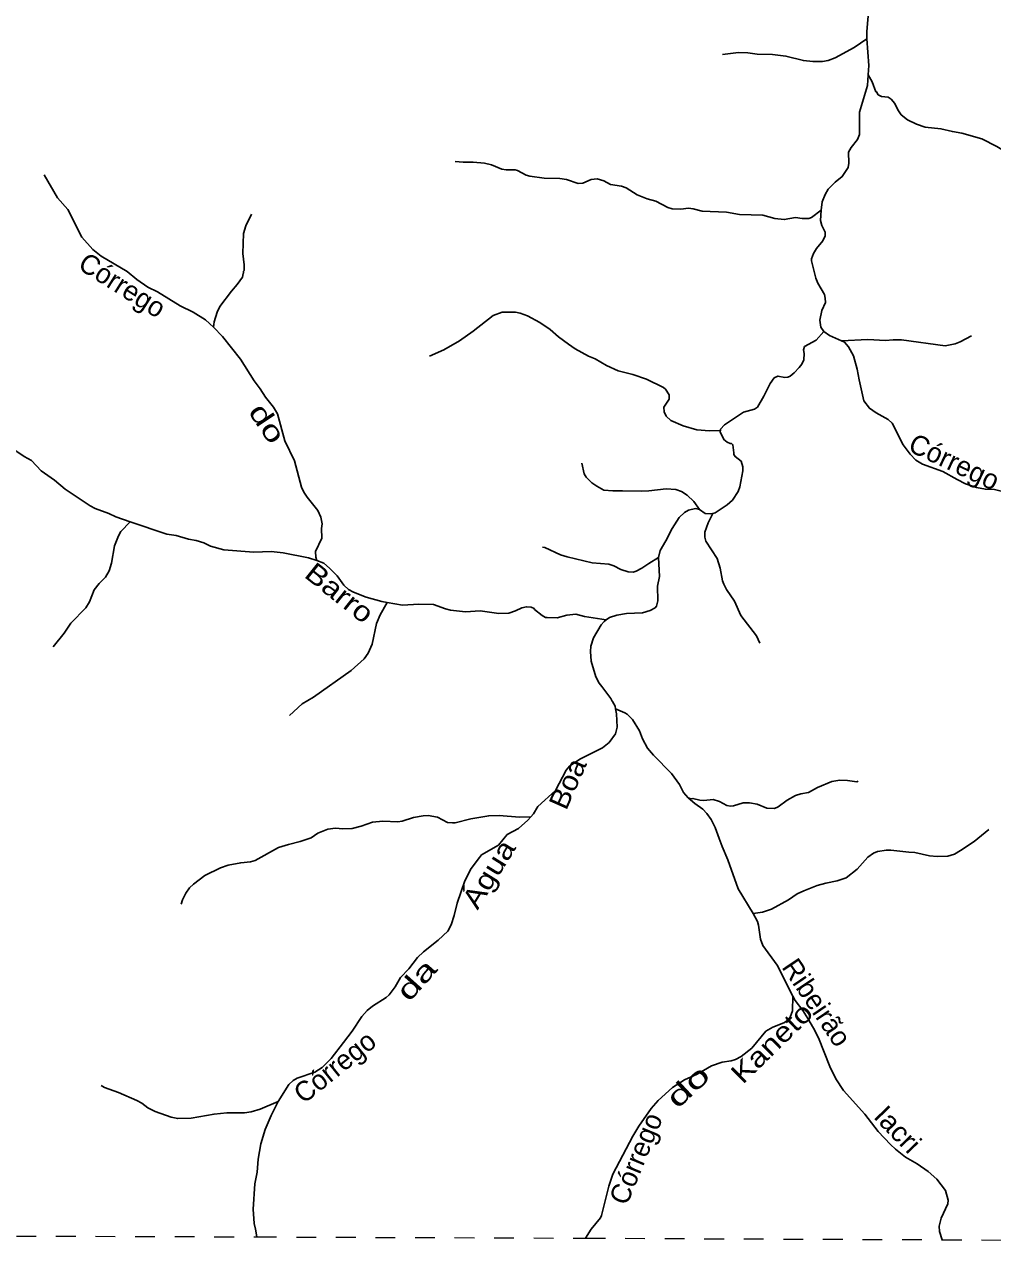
# Model space of a CAD drawing. Extents: x 551.6 to 577.6, y 7567 to 7594.7.
# Drawn here: x 561.8 to 566.69, y 7566.95 to 7573.14 of the extents above; entities that cross this region are included whole.
import ezdxf
from ezdxf.enums import TextEntityAlignment as Align

# ---------------------------------------------------------------- set-up
doc = ezdxf.new("R2010")
doc.units = 0
doc.header["$LTSCALE"] = 0.04
doc.linetypes.add('SHORT_DASHED', pattern=[2.7, 1.5, -1.2])
doc.layers.add('53', color=7, linetype='SHORT_DASHED', lineweight=13)
doc.layers.add('7', color=7, linetype='Continuous', lineweight=25)
doc.layers.add('61', color=7, linetype='Continuous')

msp = doc.modelspace()

# ---------------------------------------------------------------- linework, layer by layer
at = {"layer": '53'}
msp.add_lwpolyline([(551.613, 7567.0572), (552.9162, 7567.0524), (553.7221, 7567.0495), (554.9107, 7567.0451), (556.1477, 7567.0406), (557.2075, 7567.0367), (559.4055, 7567.0287), (559.6981, 7567.0276), (560.556, 7567.0244), (562.9715, 7567.0156), (564.6334, 7567.0092), (566.4358, 7567.0011), (566.7714, 7566.9996), (570.8595, 7566.9812), (572.5416, 7566.9737), (572.8363, 7566.9724), (573.5039, 7566.9694), (573.609, 7566.9689), (574.6855, 7566.9641), (575.0536, 7566.9624), (576.5544, 7566.9557), (577.1266, 7566.9531), (577.4204, 7566.9518)], dxfattribs=at)
at = {"layer": '7'}
for points in [[(566.0515, 7573.3763), (566.066, 7573.2266), (566.0547, 7573.1075), (566.0547, 7573.0716)], [(566.0547, 7573.0716), (565.992, 7573.0278), (565.8946, 7572.9746), (565.86, 7572.961), (565.831, 7572.9561), (565.7827, 7572.9561), (565.7345, 7572.961), (565.6459, 7572.9835), (565.5783, 7572.9916), (565.5011, 7572.994), (565.4544, 7573.0004), (565.4061, 7573.0012), (565.3264, 7572.9916)], [(566.0547, 7573.0716), (566.0652, 7572.9368), (566.0618, 7572.8891)], [(566.0618, 7572.8891), (566.058, 7572.8354), (566.0177, 7572.7002), (566.0185, 7572.5876), (566.0089, 7572.5618), (565.9759, 7572.5216), (565.963, 7572.499), (565.9646, 7572.4427), (565.9614, 7572.4202), (565.9308, 7572.3751), (565.8946, 7572.3469), (565.8592, 7572.3107), (565.8439, 7572.285), (565.8294, 7572.2463), (565.8239, 7572.2047)], [(566.536, 7572.594), (566.4877, 7572.602), (566.4298, 7572.6165), (566.3509, 7572.6246), (566.3059, 7572.6398), (566.2617, 7572.662), (566.2287, 7572.6877), (566.2125, 7572.7115), (566.1964, 7572.7437), (566.1787, 7572.7654), (566.1634, 7572.7759), (566.1288, 7572.7799), (566.1127, 7572.7887), (566.1046, 7572.8024), (566.1014, 7572.8032), (566.0821, 7572.8531), (566.0618, 7572.8891)], [(567.6241, 7572.3002), (567.5903, 7572.3195), (567.5614, 7572.3284), (567.4696, 7572.3413), (567.4245, 7572.3397), (567.3795, 7572.3316), (567.2877, 7572.3284), (567.2169, 7572.3381), (567.1493, 7572.3429), (567.0817, 7572.3542), (567.0318, 7572.359), (566.9932, 7572.3735), (566.9014, 7572.4234), (566.8451, 7572.4483), (566.7123, 7572.5264), (566.6374, 7572.565), (566.536, 7572.594)], [(564.8154, 7572.326), (564.759, 7572.3348), (564.7252, 7572.3525), (564.6914, 7572.363), (564.6616, 7572.3598), (564.619, 7572.3413), (564.5957, 7572.3397), (564.5369, 7572.3598), (564.5031, 7572.3646), (564.4242, 7572.3662), (564.3518, 7572.3775), (564.3325, 7572.3823), (564.289, 7572.4057), (564.2778, 7572.4089), (564.2327, 7572.4089), (564.2102, 7572.4121), (564.157, 7572.4338), (564.1232, 7572.4419), (564.0653, 7572.4483), (564.0138, 7572.4475), (563.9744, 7572.4507)], [(561.8964, 7572.3839), (561.9631, 7572.2673), (562.0163, 7572.2077), (562.0871, 7572.0693), (562.1426, 7572.0065), (562.1845, 7571.9727), (562.3157, 7571.8946), (562.3647, 7571.8544), (562.4195, 7571.8157), (562.4686, 7571.7916), (562.5845, 7571.7216), (562.6489, 7571.6902), (562.7116, 7571.6507), (562.7515, 7571.6142)], [(565.8239, 7572.2047), (565.7763, 7572.1674), (565.7618, 7572.1626), (565.728, 7572.1626), (565.6942, 7572.1674), (565.6379, 7572.157), (565.5896, 7572.1626), (565.53, 7572.1803), (565.4109, 7572.1835), (565.3465, 7572.1948), (565.2226, 7572.2004), (565.1775, 7572.2125), (565.1534, 7572.2149), (565.1148, 7572.2109), (565.0713, 7572.2125), (565.0488, 7572.2189), (564.9892, 7572.2503), (564.9441, 7572.2624), (564.8942, 7572.2825), (564.8379, 7572.3179), (564.8154, 7572.326)], [(565.8239, 7572.2047), (565.8214, 7572.153), (565.8286, 7572.1272), (565.8439, 7572.0942), (565.8455, 7572.0757), (565.8326, 7572.05), (565.8012, 7572.0113), (565.7859, 7571.9856), (565.7763, 7571.9582), (565.7763, 7571.9486), (565.7972, 7571.8616), (565.8069, 7571.8359), (565.8407, 7571.7795), (565.8455, 7571.7602), (565.8471, 7571.7377), (565.8278, 7571.6975), (565.8173, 7571.6492), (565.823, 7571.6129), (565.8372, 7571.5922)], [(562.945, 7572.1844), (562.9152, 7572.1256), (562.9048, 7572.087), (562.8999, 7571.9856), (562.908, 7571.9292), (562.908, 7571.9003), (562.9048, 7571.897), (562.9048, 7571.8874), (562.9015, 7571.8842), (562.8983, 7571.8665), (562.8726, 7571.8286), (562.8436, 7571.7956), (562.7848, 7571.7184), (562.7712, 7571.6894), (562.7551, 7571.6411), (562.7515, 7571.6142)], [(563.844, 7571.4673), (563.9172, 7571.4995), (563.9953, 7571.5445), (564.0645, 7571.5936), (564.1667, 7571.6725), (564.2118, 7571.6902), (564.2794, 7571.6894), (564.3019, 7571.6846), (564.3405, 7571.6701), (564.4017, 7571.6379), (564.454, 7571.6025), (564.4959, 7571.5655), (564.5466, 7571.5276), (564.5804, 7571.5043), (564.648, 7571.4673), (564.6826, 7571.4528), (564.7397, 7571.4198), (564.7977, 7571.3932), (564.8717, 7571.3747)], [(562.7515, 7571.6142), (562.7977, 7571.5671), (562.8895, 7571.4512)], [(565.8372, 7571.5922), (565.7988, 7571.5477), (565.7409, 7571.5156), (565.7344, 7571.4995), (565.7393, 7571.4801), (565.736, 7571.448), (565.7264, 7571.427), (565.7135, 7571.4093)], [(565.8372, 7571.5922), (565.8664, 7571.5719), (565.9271, 7571.5448)], [(566.5851, 7571.5695), (566.528, 7571.5397), (566.5022, 7571.53), (566.4507, 7571.5196), (566.2302, 7571.5494), (566.1884, 7571.5502), (566.1497, 7571.5461), (566.0596, 7571.551), (565.9271, 7571.5448)], [(565.9271, 7571.5448), (565.9421, 7571.5381), (565.963, 7571.514), (565.9879, 7571.4689), (566.0073, 7571.4013), (566.0161, 7571.3482), (566.0403, 7571.2411), (566.0684, 7571.2041), (566.103, 7571.1808), (566.1626, 7571.1478), (566.1827, 7571.1277), (566.2382, 7571.0182), (566.2736, 7570.9715), (566.3034, 7570.9417), (566.3364, 7570.9208), (566.4395, 7570.8838), (566.5127, 7570.8435)], [(562.8895, 7571.4512), (562.9579, 7571.3417), (562.9885, 7571.3023), (563.015, 7571.2604), (563.0561, 7571.2097), (563.0754, 7571.1759), (563.1132, 7571.0391), (563.1623, 7570.9377), (563.1977, 7570.8057), (563.209, 7570.78), (563.2251, 7570.7542), (563.2798, 7570.6866), (563.2951, 7570.6528), (563.3023, 7570.619), (563.2991, 7570.5965), (563.2999, 7570.5466), (563.2685, 7570.479), (563.2701, 7570.4508), (563.2743, 7570.4348)], [(565.7135, 7571.4093), (565.6878, 7571.382), (565.6669, 7571.3659), (565.6556, 7571.361), (565.6411, 7571.3594), (565.6057, 7571.3667), (565.5863, 7571.357), (565.5662, 7571.3289), (565.534, 7571.2645), (565.5019, 7571.2089), (565.4882, 7571.1993), (565.4318, 7571.184), (565.3361, 7571.1204), (565.3159, 7571.0979), (565.3152, 7571.0922)], [(564.8717, 7571.3747), (564.9417, 7571.3514), (565.027, 7571.3087), (565.0367, 7571.3007), (565.0552, 7571.2717), (565.0552, 7571.25), (565.0294, 7571.2097), (565.031, 7571.1856), (565.0407, 7571.1631), (565.064, 7571.1421), (565.1276, 7571.1156), (565.1952, 7571.0954), (565.2596, 7571.089), (565.3152, 7571.0922)], [(561.5793, 7571.1639), (561.6099, 7571.1373), (561.6968, 7571.0729), (561.7177, 7571.0488), (561.7394, 7571.0061), (561.7587, 7570.986), (561.795, 7570.9594), (561.832, 7570.9393), (561.8802, 7570.8878), (561.9479, 7570.8411), (562.0018, 7570.7952), (562.129, 7570.7107), (562.1547, 7570.6979), (562.2239, 7570.6721), (562.2577, 7570.6552), (562.3307, 7570.6292)], [(565.3152, 7571.0922), (565.3143, 7571.0842), (565.3328, 7571.0456), (565.3498, 7571.0327), (565.3642, 7571.0254), (565.3707, 7571.0254), (565.3787, 7571.019), (565.3827, 7570.978)], [(565.3827, 7570.978), (565.3835, 7570.9699), (565.39, 7570.9594), (565.4206, 7570.9361), (565.4286, 7570.9071), (565.4286, 7570.8878), (565.4133, 7570.8073), (565.4045, 7570.7832), (565.3755, 7570.7397), (565.3498, 7570.7156), (565.2886, 7570.6753), (565.2771, 7570.6724)], [(564.615, 7570.9256), (564.627, 7570.8717), (564.6367, 7570.8548), (564.6649, 7570.8274), (564.6898, 7570.8097), (564.7252, 7570.7904), (564.7719, 7570.7856), (564.8202, 7570.7872), (564.9152, 7570.784), (564.9538, 7570.7856), (565.0407, 7570.7961), (565.089, 7570.7928), (565.118, 7570.7824), (565.147, 7570.7647), (565.1807, 7570.7317), (565.2088, 7570.6918)], [(566.5127, 7570.8435), (566.5537, 7570.821), (566.6101, 7570.8041), (566.6551, 7570.7944), (566.7002, 7570.7928), (566.7485, 7570.7816), (566.7829, 7570.7658)], [(565.2088, 7570.6918), (565.1888, 7570.6971), (565.1542, 7570.689), (565.1341, 7570.6769), (565.1059, 7570.6512), (565.0705, 7570.5965), (565.0391, 7570.5337), (565.0109, 7570.4854), (565.0014, 7570.4499)], [(565.2771, 7570.6724), (565.2661, 7570.6697), (565.2379, 7570.6721), (565.2088, 7570.6918)], [(565.2771, 7570.6724), (565.254, 7570.6255), (565.2355, 7570.5772), (565.2355, 7570.5514), (565.2419, 7570.5313), (565.2982, 7570.4452), (565.3143, 7570.3953), (565.3256, 7570.3309), (565.332, 7570.3148), (565.3465, 7570.2882), (565.3868, 7570.2295), (565.419, 7570.1571), (565.4978, 7570.0541), (565.5139, 7570.0162)], [(562.3307, 7570.6292), (562.2843, 7570.5812), (562.2714, 7570.5595), (562.2513, 7570.508), (562.236, 7570.421), (562.2247, 7570.3824), (562.2062, 7570.3502), (562.1748, 7570.3188), (562.149, 7570.2858), (562.1257, 7570.2247), (562.1072, 7570.1957), (562.0312, 7570.1168), (561.9977, 7570.0669), (561.9414, 7569.9977)], [(562.3307, 7570.6292), (562.5169, 7570.5675), (562.5635, 7570.5602), (562.6263, 7570.5417), (562.665, 7570.5353), (562.7036, 7570.524)], [(562.7036, 7570.524), (562.7374, 7570.5071), (562.805, 7570.4886), (562.9563, 7570.4757), (563.0432, 7570.479), (563.1044, 7570.4733), (563.2331, 7570.4484), (563.2743, 7570.4348)], [(564.4154, 7570.5015), (564.4275, 7570.5007), (564.5063, 7570.4637), (564.5401, 7570.4532), (564.6673, 7570.4226), (564.751, 7570.4162), (564.7767, 7570.4073), (564.8113, 7570.388), (564.8492, 7570.3768), (564.8733, 7570.376), (564.8894, 7570.3808), (564.9184, 7570.3953), (564.9538, 7570.4194), (565.0014, 7570.4499)], [(563.2743, 7570.4348), (563.3096, 7570.4202), (563.3393, 7570.396)], [(565.0014, 7570.4499), (565.0069, 7570.3534), (564.9972, 7570.3051), (564.9989, 7570.2311), (564.9924, 7570.2037), (564.986, 7570.1957), (564.9602, 7570.1812), (564.9216, 7570.1699), (564.8395, 7570.1659), (564.7912, 7570.1579), (564.755, 7570.1458), (564.738, 7570.1342)], [(563.3393, 7570.396), (563.3772, 7570.3567), (563.411, 7570.31), (563.4343, 7570.2882), (563.4601, 7570.2737), (563.5245, 7570.2488), (563.6033, 7570.2263), (563.6297, 7570.2218)], [(563.6297, 7570.2218), (563.5945, 7570.1603), (563.5768, 7570.1152), (563.555, 7570.0106), (563.5349, 7569.9655), (563.5148, 7569.9365), (563.4488, 7569.8778), (563.2573, 7569.7434), (563.2009, 7569.7096), (563.1358, 7569.6508)], [(563.6297, 7570.2218), (563.708, 7570.2086), (563.7901, 7570.2134), (563.8641, 7570.2118), (563.9253, 7570.1892), (563.951, 7570.1828), (564.0267, 7570.1756), (564.1007, 7570.1796), (564.1941, 7570.1667), (564.2456, 7570.1683), (564.2794, 7570.1796), (564.3116, 7570.1957), (564.3341, 7570.2005), (564.3582, 7570.1981), (564.3727, 7570.1925), (564.3759, 7570.1868), (564.4146, 7570.157), (564.4315, 7570.1466), (564.4387, 7570.1466)], [(564.4387, 7570.1466), (564.4902, 7570.145), (564.5385, 7570.1587), (564.5836, 7570.1627), (564.6287, 7570.1514), (564.738, 7570.1342)], [(564.738, 7570.1342), (564.7268, 7570.1265), (564.7123, 7570.1096), (564.6737, 7570.0428), (564.6608, 7570.0009), (564.6584, 7569.9736), (564.6624, 7569.9253), (564.685, 7569.8464), (564.7019, 7569.8142), (564.7148, 7569.7981)], [(564.7148, 7569.7981), (564.7606, 7569.737), (564.7671, 7569.7225), (564.7703, 7569.7217), (564.7828, 7569.6972), (564.7843, 7569.6853)], [(564.7843, 7569.6853), (564.7896, 7569.6597), (564.7936, 7569.5921), (564.7848, 7569.5583), (564.7526, 7569.514), (564.7188, 7569.4875), (564.6045, 7569.4295), (564.5522, 7569.3949), (564.5361, 7569.3748), (564.4806, 7569.2726), (564.3912, 7569.1905), (564.3695, 7569.1535), (564.3565, 7569.1382)], [(564.7843, 7569.6853), (564.8323, 7569.6645), (564.8435, 7569.6573), (564.8701, 7569.6307), (564.9055, 7569.5728), (564.9216, 7569.5325), (564.9473, 7569.4859), (564.9763, 7569.4496), (565.0681, 7569.3571), (565.1083, 7569.3024), (565.1292, 7569.2621), (565.1525, 7569.2345)], [(566.0121, 7569.3193), (566.0041, 7569.316), (565.9582, 7569.3225), (565.918, 7569.3233), (565.8777, 7569.3176), (565.8053, 7569.2871), (565.7602, 7569.2621), (565.7216, 7569.2557), (565.6942, 7569.246), (565.6524, 7569.2227), (565.6065, 7569.1889), (565.588, 7569.1808), (565.5494, 7569.1824), (565.5011, 7569.2026), (565.4624, 7569.209), (565.4302, 7569.209), (565.382, 7569.1945), (565.3659, 7569.1929), (565.3482, 7569.1961), (565.3103, 7569.2154), (565.2789, 7569.2267), (565.2307, 7569.2219), (565.2113, 7569.2235)], [(565.1525, 7569.2345), (565.1856, 7569.2058), (565.2266, 7569.1768), (565.2467, 7569.1551), (565.2677, 7569.1253), (565.2894, 7569.0851), (565.3095, 7569.0287)], [(565.2113, 7569.2235), (565.1759, 7569.2315), (565.1662, 7569.2299), (565.1525, 7569.2345)], [(564.3565, 7569.1382), (564.2987, 7569.1366), (564.1957, 7569.1462), (564.1442, 7569.1438), (564.054, 7569.1285), (563.9736, 7569.1084), (563.9607, 7569.1076), (563.9349, 7569.1108), (563.885, 7569.1366), (563.8383, 7569.1446), (563.8126, 7569.1438), (563.7627, 7569.135), (563.7064, 7569.1172), (563.6838, 7569.114), (563.6082, 7569.1172), (563.5567, 7569.1124), (563.4987, 7569.0915), (563.4537, 7569.0802), (563.407, 7569.0786), (563.3683, 7569.0818), (563.3297, 7569.0762), (563.2806, 7569.0553), (563.246, 7569.0327), (563.1897, 7569.0134), (563.1317, 7568.9981)], [(564.3565, 7569.1382), (564.3421, 7569.1213), (564.2947, 7569.0802), (564.2367, 7569.0488), (564.1925, 7568.9957), (564.1071, 7568.9458), (564.0975, 7568.9338)], [(566.672, 7569.0746), (566.5972, 7569.0134), (566.5296, 7568.9684), (566.499, 7568.9506), (566.4652, 7568.9402), (566.4105, 7568.9386), (566.3719, 7568.9418), (566.2978, 7568.9587), (566.2672, 7568.9595), (566.1771, 7568.97), (566.1546, 7568.9708), (566.1095, 7568.9627), (566.0894, 7568.9555), (566.0604, 7568.9354), (566.0057, 7568.8734), (565.9501, 7568.8299), (565.9051, 7568.8146), (565.8487, 7568.8042), (565.8037, 7568.7913), (565.736, 7568.7647)], [(563.1317, 7568.9981), (563.0802, 7568.9836), (562.9627, 7568.9185), (562.9402, 7568.9112), (562.8903, 7568.9064), (562.8259, 7568.8943), (562.7873, 7568.8814), (562.7084, 7568.8428), (562.6513, 7568.7985), (562.6311, 7568.7792), (562.6118, 7568.7535), (562.5957, 7568.7197), (562.5893, 7568.698)], [(565.3095, 7569.0287), (565.3232, 7568.9885), (565.353, 7568.9209), (565.4045, 7568.7744), (565.481, 7568.6509)], [(564.0975, 7568.9338), (564.0548, 7568.8774), (564.0226, 7568.8147), (563.9848, 7568.702), (563.9695, 7568.6408), (563.9534, 7568.5925), (563.9365, 7568.5611), (563.8874, 7568.5153), (563.8142, 7568.4565), (563.7844, 7568.4283), (563.7402, 7568.3704), (563.6983, 7568.327), (563.6709, 7568.2795), (563.6404, 7568.2392), (563.6251, 7568.2255), (563.5558, 7568.1813), (563.5293, 7568.1596), (563.5027, 7568.129), (563.4536, 7568.0549), (563.4102, 7567.9978)], [(565.736, 7568.7647), (565.7039, 7568.7494), (565.6588, 7568.7189), (565.5735, 7568.6722), (565.5284, 7568.6569), (565.481, 7568.6509)], [(565.481, 7568.6509), (565.5027, 7568.6102), (565.5083, 7568.5909), (565.5179, 7568.5201), (565.53, 7568.4879), (565.6016, 7568.3881), (565.6813, 7568.233)], [(565.6813, 7568.233), (565.6797, 7568.1579), (565.6676, 7568.1257), (565.654, 7568.1088), (565.6363, 7568.0968), (565.5799, 7568.0758), (565.5445, 7568.0549), (565.4737, 7567.9688), (565.4206, 7567.9278), (565.3916, 7567.9117), (565.3691, 7567.9052), (565.324, 7567.8988), (565.2693, 7567.8795), (565.1969, 7567.8376), (565.1341, 7567.8086), (565.0729, 7567.77), (565.0005, 7567.7048), (564.9658, 7567.6638), (564.9031, 7567.5753), (564.8725, 7567.5238)], [(565.6813, 7568.233), (565.6926, 7568.2111), (565.7312, 7568.1596), (565.757, 7568.1193)], [(565.757, 7568.1193), (565.7859, 7568.071), (565.8109, 7568.0211), (565.8688, 7567.8763), (565.8978, 7567.8151), (565.938, 7567.7555), (566.0451, 7567.6356), (566.1119, 7567.5479), (566.1755, 7567.4819), (566.2004, 7567.4586), (566.2511, 7567.4191), (566.3091, 7567.3853), (566.3654, 7567.3459), (566.4089, 7567.3065)], [(563.4102, 7567.9978), (563.3474, 7567.9165), (563.3024, 7567.8714), (563.2653, 7567.8489), (563.1752, 7567.8175), (563.1543, 7567.8054), (563.1325, 7567.7861), (563.08, 7567.6992)], [(563.08, 7567.6992), (562.9885, 7567.6606), (562.9434, 7567.6477), (562.9096, 7567.6429), (562.8195, 7567.6429), (562.7551, 7567.6364), (562.6392, 7567.6163), (562.5716, 7567.6139), (562.5378, 7567.6203), (562.4573, 7567.6485), (562.4211, 7567.667), (562.3897, 7567.6911), (562.364, 7567.7056), (562.2722, 7567.7451), (562.2014, 7567.7708), (562.1845, 7567.7805)], [(563.08, 7567.6992), (563.044, 7567.6284), (563.0142, 7567.5576), (562.9917, 7567.4867), (562.9788, 7567.4079), (562.9724, 7567.3419), (562.9611, 7567.2839), (562.953, 7567.1552), (562.9579, 7567.0835), (562.9643, 7567.0554), (562.9715, 7567.0156)], [(564.8725, 7567.5238), (564.7719, 7567.3322), (564.751, 7567.2711), (564.714, 7567.123), (564.7083, 7567.1117), (564.6616, 7567.0554), (564.6334, 7567.0092)], [(566.4089, 7567.3065), (566.4523, 7567.2501), (566.4668, 7567.2018), (566.4652, 7567.1825), (566.4314, 7567.1101), (566.4217, 7567.0699), (566.4225, 7567.0425), (566.4358, 7567.0011)]]:
    msp.add_lwpolyline(points, dxfattribs=at)

# ---------------------------------------------------------------- texts
at = {"layer": '61'}
for s, rotation, p in [('Córrego', 327.767, (562.2649, 7571.7839)), ('Córrego', 334.925, (566.4764, 7570.888)), ('Ribeirão', 303.998, (565.761, 7568.1728)), ('Córrego', 38.895, (563.3967, 7567.836)), ('Córrego', 67.588, (564.9338, 7567.3926))]:
    msp.add_text(s, height=0.1, rotation=rotation, dxfattribs=at).set_placement(p, align=Align.CENTER)
for s, rotation, width, p in [('do', 303.69, 1.4, (562.9826, 7571.1001)), ('Barro', 321.479, 1.2, (563.3588, 7570.2321)), ('Boa', 66.058, 1.1, (564.5883, 7569.2865)), ('Água', 58.217, 1.2, (564.186, 7568.8236)), ('da', 48.189, 1.5, (563.8155, 7568.282)), ('Kaneto', 44.321, 1.2, (565.6097, 7567.9607)), ('do', 43.113, 1.6, (565.185, 7567.74)), ('Iacri', 313.851, 1.05, (566.176, 7567.5244))]:
    msp.add_text(s, height=0.1, rotation=rotation, dxfattribs=dict(at, width=width)).set_placement(p, align=Align.CENTER)

doc.saveas('drawing.dxf')
